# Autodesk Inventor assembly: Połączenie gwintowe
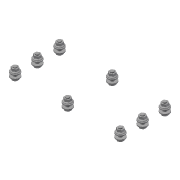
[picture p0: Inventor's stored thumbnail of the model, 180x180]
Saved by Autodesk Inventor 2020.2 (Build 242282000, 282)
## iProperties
Manager: www.cadconsulting.pl
Company: Fabian Stasiak CAD Consulting
ClientObjectVersion: 1
Created: 2011-01
Part Number: Połączenie gwintowe
Document SubType Name: Assembly
Designer: F.Stasiak
Author: F.Stasiak
Subject: Zbiór ćwiczeń. Autodesk Inventor 2020. Kurs podstawowy
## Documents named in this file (4)
- C:\2020_Kurs_podstawowy\R6 Zespoły\Kolizja\100-000\Design Accelerator\Połączenie gwintowe6.iam
- C:\2020_Kurs_podstawowy\Zasoby\Content Center Files\pl-PL\DIN 6796\DIN 6796 - 12.ipt
- C:\2020_Kurs_podstawowy\Zasoby\Content Center Files\pl-PL\DIN EN 24 017\ISO 4017 - M12 x 30DIN EN.ipt
- C:\2020_Kurs_podstawowy\Zasoby\Content Center Files\pl-PL\DIN 6923\DIN 6923 - M12 x 1,75.ipt
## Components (32 placed, 3 different names)
1. DIN 6796 12:1
2. DIN EN 24017 M12 x 30:1
3. DIN 6796 12:2
4. DIN 6923 M12:1
5. DIN EN 24017 M12 x 30:2
6. DIN EN 24017 M12 x 30:3
7. DIN EN 24017 M12 x 30:4
8. DIN EN 24017 M12 x 30:5
9. DIN EN 24017 M12 x 30:6
10. DIN EN 24017 M12 x 30:7
11. DIN EN 24017 M12 x 30:8
12. DIN 6796 12:3
13. DIN 6796 12:4
14. DIN 6796 12:5
15. DIN 6796 12:6
16. DIN 6796 12:7
17. DIN 6796 12:8
18. DIN 6796 12:9
19. DIN 6796 12:10
20. DIN 6796 12:11
21. DIN 6796 12:12
22. DIN 6796 12:13
23. DIN 6796 12:14
24. DIN 6796 12:15
25. DIN 6796 12:16
26. DIN 6923 M12:2
27. DIN 6923 M12:3
28. DIN 6923 M12:4
29. DIN 6923 M12:5
30. DIN 6923 M12:6
31. DIN 6923 M12:7
32. DIN 6923 M12:8
